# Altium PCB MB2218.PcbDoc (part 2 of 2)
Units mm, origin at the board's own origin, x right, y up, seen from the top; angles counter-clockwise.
Board outline 43 x 47 mm, 4 copper layers (Top Layer, Signal Layer 1, Signal Layer 2, Bottom Layer), stack 1.539 mm thick; 90 components, 71 nets, 361 pads, 605 vias.
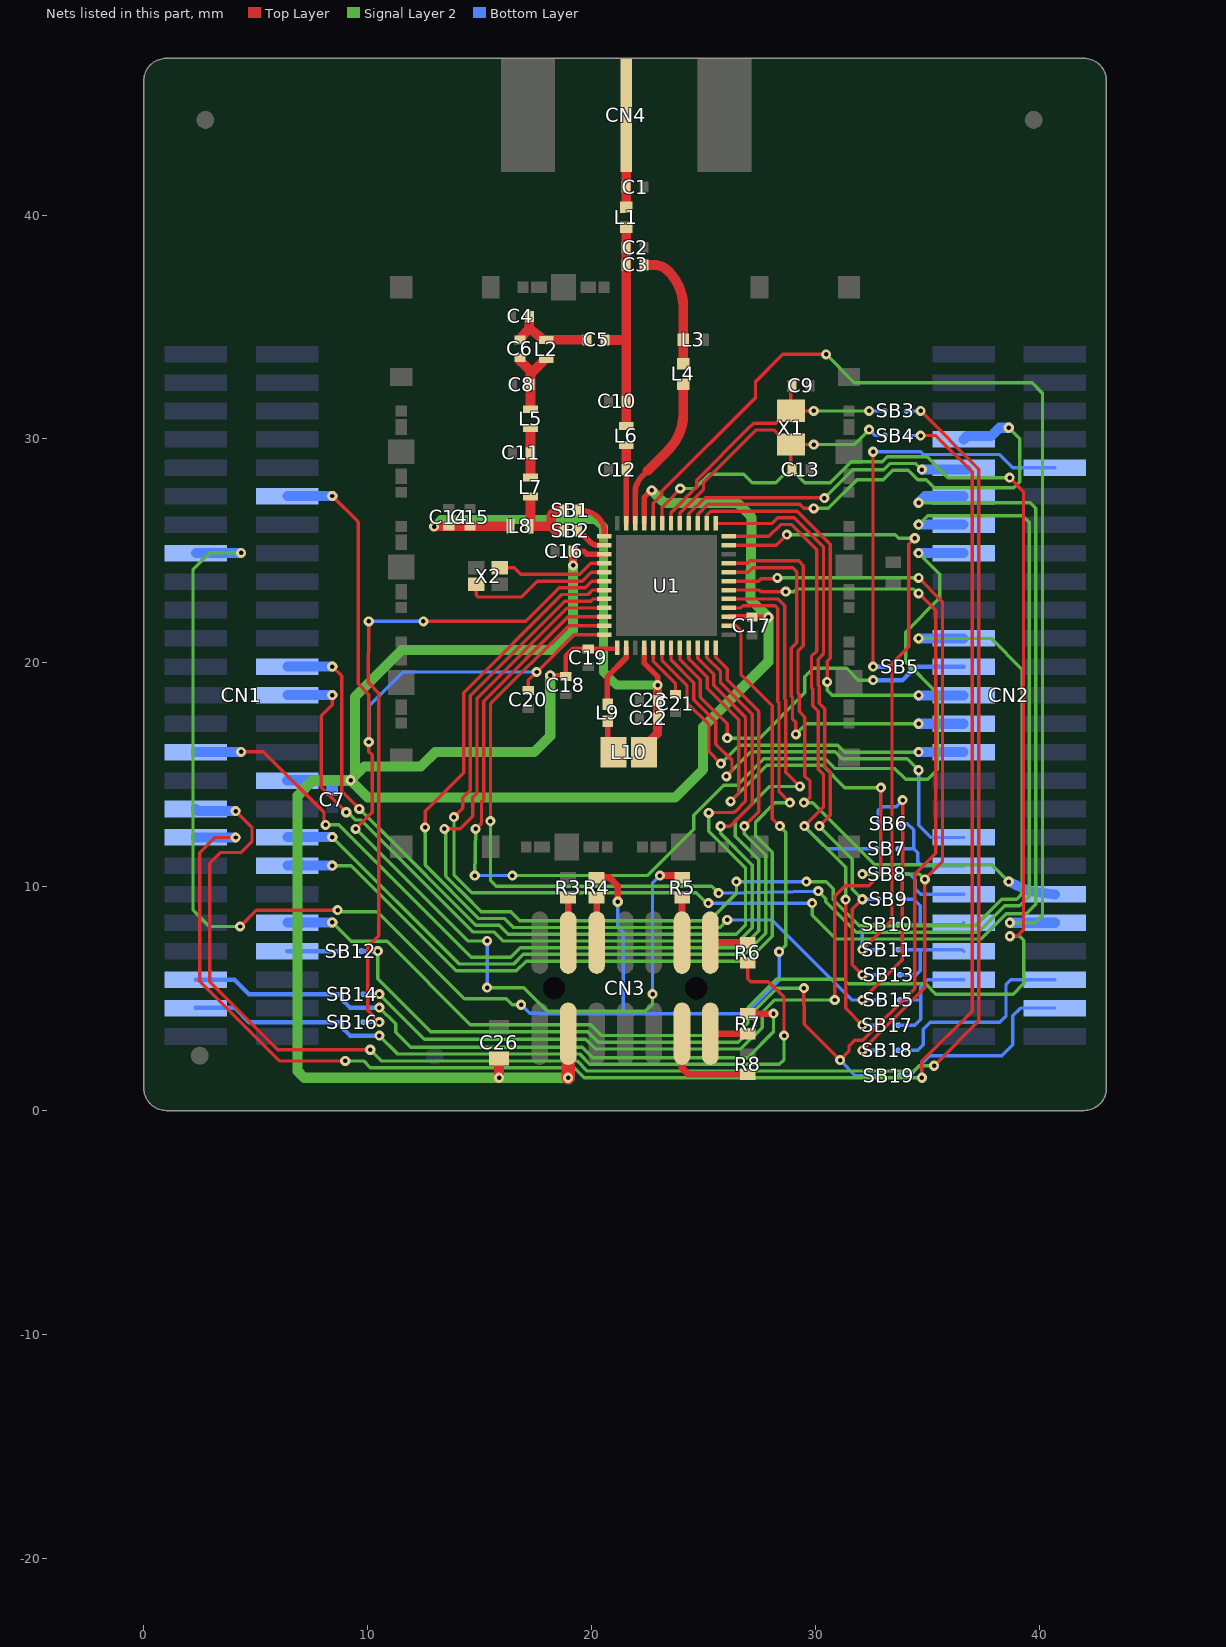
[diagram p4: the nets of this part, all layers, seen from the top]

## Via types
v1: diameter 0.45, hole 0.2, Top Layer to Bottom Layer, tented both sides, 605 vias

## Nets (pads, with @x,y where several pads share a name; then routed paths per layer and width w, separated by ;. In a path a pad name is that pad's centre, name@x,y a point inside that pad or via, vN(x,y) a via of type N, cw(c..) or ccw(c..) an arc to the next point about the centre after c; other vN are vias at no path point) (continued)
GPIO6/SWCLK: CN1.15 R4.2 U1.2 | length 73.1
  Top Layer w0.15: v1(4.301,8.22) 5.033,8.951 v1(8.658,8.951) ; U1.2@26.125,21.65 26.15,21.625 26.493,21.625 26.675,21.443 26.675,19.475 26.779,19.371 28.075,18.075 28.075,13.035 v1(28.41,12.7)
  Top Layer w0.3: R4.2@20.225,10.4 20.231,10.406 20.8,10.406 21.17,10.035 v1(21.17,9.326)
  Signal Layer 2 w0.15: v1(4.301,8.22) 2.931,8.22 2.2,8.951 2.2,24.175 2.935,24.91 v1(4.35,24.91) ; v1(8.658,8.951) 8.739,8.951 8.815,8.875 8.838,8.875 10.367,8.875 cw(c10.367,8.725) 10.473,8.831 10.854,8.45 14.266,5.037 ccw(c14.372,5.144) 14.372,4.994 15.873,5 16.186,5 16.461,4.725 v1(16.855,4.725) ; v1(28.381,7.093) 28.675,7.388 28.675,11.032 28.675,12.435 v1(28.41,12.7)
  Bottom Layer w0.15: v1(16.855,4.725) 17.241,4.339 17.7,4.339 ccw(c17.763,4.475) 17.763,4.325 21.425,4.325 ; v1(21.17,9.326) 21.17,8.212 21.425,7.958 21.425,4.325 ; v1(28.381,7.093) 28.381,5.816 26.889,4.325 21.425,4.325
  Bottom Layer w0.45: CN1.15@2.343,24.91 v1(4.35,24.91)
GPIO11: CN1.24 U1.46 | length 43.9
  Top Layer w0.15: v1(8.42,19.83) 8.838,19.412 8.838,14.265 v1(9.625,13.478) ; U1.46@24.75,20.675 24.75,20.201 25.463,19.489 25.463,18.99 26.875,17.578 26.875,13.811 26.436,13.372 cw(c26.33,13.478) 26.335,13.328 v1(25.236,13.294)
  Signal Layer 2 w0.15: v1(9.625,13.478) 10.434,12.669 10.439,12.669 14.833,8.275 15.873,8.275 16.273,7.875 26.468,7.875 26.875,8.282 26.875,10.838 25.236,12.477 v1(25.236,13.294)
  Bottom Layer w0.45: CN1.24@6.413,19.83 v1(8.42,19.83)
GPIO12: CN1.26 U1.47 | length 43.4
  Top Layer w0.15: v1(8.42,18.56) 8.42,18.124 7.925,17.629 7.925,14.443 v1(9.045,13.323) ; U1.47@25.15,20.675 25.15,20.226 25.763,19.613 25.763,19.114 27.175,17.702 27.175,13.686 26.187,12.699 v1(25.763,12.699)
  Signal Layer 2 w0.15: v1(9.045,13.323) 9.102,13.323 9.445,12.98 9.698,12.98 14.703,7.975 15.635,7.975 16.035,7.575 26.593,7.575 27.175,8.157 27.175,10.963 25.763,12.375 v1(25.763,12.699)
  Bottom Layer w0.45: CN1.26@6.413,18.56 v1(8.42,18.56)
GPIO14: CN1.29 U1.5 | length 49.6
  Top Layer w0.15: v1(4.35,16.02) 5.345,16.02 8.05,13.315 8.05,12.909 8.118,12.841 v1(8.118,12.76) ; U1.5@26.125,22.85 28.323,22.85 28.625,22.548 28.625,18.386 28.675,18.336 28.675,15.11 v1(29.31,14.475)
  Signal Layer 2 w0.15: v1(8.118,12.76) 8.716,12.76 14.631,6.845 16.396,6.845 16.826,7.275 26.717,7.275 27.475,8.033 27.475,11.208 26.425,12.258 26.425,12.936 27.964,14.475 v1(29.31,14.475)
  Bottom Layer w0.45: CN1.29@2.343,16.02 v1(4.35,16.02)
GPIO15/OSC32_IN: CN1.33 SB3.2 | length 77
  Top Layer w0.15: v1(4.101,13.372) 4.818,12.655 4.836,12.655 4.836,12.025 4.336,11.525 3.421,11.525 2.95,11.054 2.95,5.75 5.985,2.715 v1(10.115,2.715) ; v1(34.7,31.25) 37.3,28.65 37.3,4 v1(35.3,2)
  Signal Layer 2 w0.15: v1(10.115,2.715) 10.615,2.215 19.354,2.215 19.804,1.765 34.398,1.765 34.633,2 v1(35.3,2)
  Bottom Layer w0.15: SB3.2@34,31.25 SB3.2@34.075,31.25 v1(34.7,31.25)
  Bottom Layer w0.45: CN1.33@2.331,13.468 2.427,13.372 v1(4.101,13.372)
GPIO16/OSC32_OUT: CN1.35 SB4.2 | length 75.1
  Top Layer w0.15: v1(4.101,12.195) 3.17,12.195 2.5,11.525 2.5,5.776 6.061,2.215 v1(9,2.215) ; v1(34.7,30.15) 35.376,30.15 37,28.526 37,4.437 34.757,2.194 v1(34.757,1.465)
  Signal Layer 2 w0.15: v1(9,2.215) 9.815,2.215 10.115,1.915 19.229,1.915 19.679,1.465 v1(34.757,1.465)
  Bottom Layer w0.15: SB4.2@34,30.15 SB4.2@34.075,30.15 v1(34.7,30.15)
  Bottom Layer w0.45: CN1.35@2.331,12.198 4.098,12.198 v1(4.101,12.195)
GPIO17: CN1.36 U1.48 | length 38.5
  Top Layer w0.15: U1.48@25.55,20.675 25.55,20.25 26.063,19.737 26.063,19.239 27.475,17.826 27.475,13.35 v1(26.825,12.7)
  Signal Layer 2 w0.15: v1(8.42,12.21) 14.085,6.545 16.52,6.545 16.95,6.975 26.841,6.975 27.775,7.909 27.775,11.404 26.825,12.354 v1(26.825,12.7)
  Bottom Layer w0.45: CN1.36@6.413,12.21 v1(8.42,12.21)
GPIO18: CN1.38 U1.4 | length 42.7
  Top Layer w0.15: U1.4@26.125,22.45 26.675,22.45 26.775,22.55 28.199,22.55 28.325,22.424 28.325,18.262 28.375,18.212 28.375,17.869 28.375,17.539 28.375,14.235 v1(28.86,13.75)
  Signal Layer 2 w0.15: v1(8.42,10.94) 9.266,10.94 13.961,6.245 16.644,6.245 17.074,6.675 26.965,6.675 28.075,7.785 28.075,11.528 27.325,12.278 27.325,12.885 28.19,13.75 v1(28.86,13.75)
  Bottom Layer w0.45: CN1.38@6.413,10.94 v1(8.42,10.94)
GPIO21: CN1.42 U1.19 | length 78.9
  Top Layer w0.15: U1.19@23.15,26.225 23.15,26.95 23.552,27.352 ccw(c23.446,27.458) 23.554,27.354 v1(23.964,27.785) ; v1(38.672,28.273) 39.296,27.649 39.296,8.073 39.007,7.784 v1(38.686,7.784)
  Signal Layer 2 w0.15: v1(8.42,8.4) 9.261,7.559 10.866,7.559 14.587,3.838 19.964,3.838 20.451,3.351 26.424,3.351 26.99,3.917 26.99,4.601 28.251,5.862 28.949,5.862 28.953,5.865 31.272,5.865 31.475,5.663 34.92,5.663 35.383,5.2 38.828,5.2 39.312,5.684 39.312,7.598 39.126,7.784 v1(38.686,7.784) ; v1(23.964,27.785) 24.62,27.785 25.23,28.396 cw(c25.313,28.27) 25.313,28.42 26.8,28.42 27.183,28.038 28.228,28.038 28.611,28.42 29.143,28.42 29.526,28.038 30.66,28.038 31.598,28.976 32.981,28.976 33.206,29.2 34.995,29.2 35.923,28.273 v1(38.672,28.273)
  Bottom Layer w0.45: CN1.42@6.413,8.4 v1(8.42,8.4)
GPIO22: CN1.44 SB12.2 | length 2.4
  Bottom Layer w0.2: CN1.44@6.401,7.118 6.408,7.125 SB12.2@8.75,7.125
GPIO23/VCP1_RX: CN1.45 R7.1 SB14.1 | length 30
  Top Layer w0.3: R7.1@26.975,4.325 v1(28.128,4.325)
  Signal Layer 2 w0.15: v1(10.525,4.6) 11.256,3.869 11.256,3.498 11.929,2.825 19.592,2.825 20.052,2.365 26.984,2.365 28.128,3.509 v1(28.128,4.325)
  Bottom Layer w0.2: CN1.45@2.331,5.848 4.052,5.848 4.7,5.2 SB14.1@8.825,5.2 8.835,5.19 8.835,4.974 9.211,4.598 10.523,4.598 v1(10.525,4.6)
GPIO24/VCP1_TX: CN1.47 R6.2 SB16.1 | length 33
  Top Layer w0.15: R6.2@26.975,6.6 26.975,5.882 27.107,5.75 27.899,5.75 28.6,5.049 v1(28.6,3.35)
  Signal Layer 2 w0.15: v1(10.525,3.35) 11.35,2.525 19.468,2.525 19.928,2.065 28.387,2.065 28.6,2.278 v1(28.6,3.35)
  Bottom Layer w0.2: CN1.47@2.331,4.598 4.052,4.598 4.7,3.95 SB16.1@8.825,3.95 8.835,3.94 8.835,3.724 9.211,3.348 10.523,3.348 v1(10.525,3.35)
GPIO28: CN2.7 U1.15 | length 21
  Top Layer w0.15: U1.15@24.75,26.225 24.75,26.624 25.201,27.075 29.31,27.075 29.485,26.9 v1(29.925,26.9)
  Signal Layer 2 w0.15: v1(29.925,26.9) 30.583,26.9 31.858,28.175 33.029,28.175 33.454,28.6 34.148,28.6 34.573,28.175 34.95,28.175 35.302,27.823 38.858,27.823 39.122,28.086 39.122,30.015 v1(38.637,30.5)
  Bottom Layer w0.45: CN2.7@36.621,29.978 36.766,30.123 37.848,30.123 38.225,30.5 v1(38.637,30.5)
GPIO29: CN2.9 U1.16 | length 13.9
  Top Layer w0.15: U1.16@24.35,26.225 24.35,26.649 25.076,27.375 30.378,27.375 v1(30.4,27.353)
  Signal Layer 2 w0.15: v1(30.4,27.353) 31.672,28.625 33.055,28.625 33.33,28.9 34.484,28.9 v1(34.759,28.625)
  Bottom Layer w0.45: v1(34.759,28.625) CN2.9@36.766,28.625
GPIO30: CN2.10 SB5.1 | length 18.7
  Top Layer w0.15: v1(32.575,19.825) v1(32.575,29.426)
  Bottom Layer w0.15: v1(32.575,29.426) 34.708,29.426 34.759,29.375 34.831,29.303 38.229,29.303 38.824,28.708 CN2.10@40.691,28.708
  Bottom Layer w0.2: v1(32.575,19.825) SB5.1@33.3,19.825
GPIO31: CN2.11 U1.32 | length 69.4
  Top Layer w0.15: v1(13.856,13.107) 13.856,13.13 13.879,13.13 14.249,13.5 14.249,13.965 14.585,14.301 14.585,18.535 18.8,22.75 19.967,22.75 20.067,22.85 U1.32@20.575,22.85
  Signal Layer 2 w0.15: v1(13.856,13.107) 13.856,10.525 14.655,9.726 24.684,9.726 25.19,9.22 25.219,9.249 v1(25.219,9.264) ; v1(29.858,9.264) 29.858,8.727 30.924,7.66 37.391,7.66 38.518,8.788 39.413,8.788 39.845,9.22 39.845,26.9 39.595,27.15 v1(34.614,27.15)
  Bottom Layer w0.15: v1(25.219,9.264) v1(29.858,9.264)
  Bottom Layer w0.45: v1(34.614,27.15) 34.902,27.438 CN2.11@36.621,27.438
GPIO33: CN2.13 U1.35 | length 64.1
  Top Layer w0.15: v1(15.485,12.925) 15.485,18.1 cw(c15.635,18.1) 15.529,18.206 18.973,21.65 U1.35@20.575,21.65
  Signal Layer 2 w0.15: v1(15.485,12.925) 15.485,10.291 15.75,10.026 25.361,10.026 v1(25.68,9.708) ; v1(30.127,9.801) 30.467,9.461 30.467,9.318 31.825,7.96 37.266,7.96 38.451,9.145 39.12,9.145 39.545,9.57 39.545,26.273 39.25,26.568 35.014,26.568 34.618,26.172 34.618,26.168 v1(34.614,26.168)
  Bottom Layer w0.15: v1(25.68,9.708) v1(30.127,9.801)
  Bottom Layer w0.45: v1(34.614,26.168) CN2.13@36.621,26.168
GPIO34: CN2.15 U1.34 | length 51.9
  Top Layer w0.15: v1(14.825,12.58) 15.085,12.84 15.085,13.788 15.185,13.888 15.185,18.287 18.949,22.05 U1.34@20.575,22.05
  Signal Layer 2 w0.15: v1(14.784,10.498) v1(14.825,12.58) ; v1(16.461,10.498) 22.489,10.498 24.563,12.571 24.563,13.186 25.902,14.525 26.5,14.525 27.695,15.72 30.443,15.72 30.888,15.275 33.554,15.275 34.029,14.8 35.014,14.8 35.441,15.227 35.441,18.646 34.029,20.058 34.029,21.373 35.562,22.906 35.562,23.95 v1(34.614,24.898)
  Bottom Layer w0.15: v1(14.784,10.498) v1(16.461,10.498)
  Bottom Layer w0.45: v1(34.614,24.898) CN2.15@36.621,24.898
GPIO37: CN2.21 U1.33 | length 62.9
  Top Layer w0.15: v1(13.425,12.58) 14.132,12.58 14.7,13.148 14.7,13.992 14.885,14.177 14.885,18.411 18.924,22.45 U1.33@20.575,22.45
  Signal Layer 2 w0.15: v1(13.425,12.58) 13.483,12.523 13.483,10.474 13.72,10.237 14.284,9.672 15.082,8.875 16.398,8.875 16.798,8.475 25.256,8.475 26.475,9.694 v1(26.475,10.225) ; v1(29.597,10.225) 30.49,10.225 30.8,9.915 30.8,9.409 31.949,8.26 37.142,8.26 38.327,9.445 38.996,9.445 39.245,9.694 39.245,19.696 37.853,21.088 v1(34.614,21.088)
  Bottom Layer w0.15: v1(26.475,10.225) v1(29.597,10.225)
  Bottom Layer w0.45: v1(34.614,21.088) CN2.21@36.621,21.088
GPIO39: CN2.23 SB5.2 U1.44 | length 17.8
  Top Layer w0.15: U1.44@23.95,20.675 23.95,20.15 24.26,19.84 24.263,19.84 24.7,19.403 24.7,19.4 24.863,19.237 24.863,18.471 26.063,17.271 v1(26.063,16.636)
  Signal Layer 2 w0.15: v1(26.063,16.636) 27.508,16.636 29.526,18.654 29.526,19.372 29.906,19.752 31.39,19.752 31.918,19.225 v1(32.575,19.225)
  Bottom Layer w0.2: v1(32.575,19.225) 32.577,19.223 33.889,19.223 34.265,19.599 34.265,19.815 SB5.2@34.275,19.825 ; SB5.2@34.275,19.818 CN2.23@36.621,19.818
GPIO41: CN2.25 U1.14 | length 19.3
  Top Layer w0.15: U1.14@25.15,26.225 25.15,26.599 25.326,26.775 29.186,26.775 30.66,25.301 30.66,20.209 30.525,20.074 v1(30.525,19.151)
  Signal Layer 2 w0.15: v1(30.525,19.151) 30.525,18.776 30.753,18.548 v1(34.614,18.548)
  Bottom Layer w0.45: v1(34.614,18.548) CN2.25@36.621,18.548
GPIO42: CN2.27 U1.8 | length 18.3
  Top Layer w0.15: U1.8@26.125,24.05 26.992,24.05 27.192,24.25 28.987,24.25 29.16,24.077 29.16,20.89 28.925,20.654 28.925,18.51 28.975,18.46 28.975,17.494 29.125,17.344 v1(29.125,16.806)
  Signal Layer 2 w0.15: v1(29.125,16.806) 29.597,17.278 v1(34.614,17.278)
  Bottom Layer w0.45: v1(34.614,17.278) CN2.27@36.621,17.278
GPIO44: CN2.29 U1.42 | length 17.6
  Top Layer w0.15: U1.42@23.15,20.675 23.15,20.101 24.263,18.989 24.263,18.223 25.25,17.236 25.25,16.027 v1(25.777,15.5)
  Signal Layer 2 w0.15: v1(25.777,15.5) 26.597,16.32 31.001,16.32 31.313,16.008 v1(34.614,16.008)
  Bottom Layer w0.45: v1(34.614,16.008) CN2.29@36.621,16.008
GPIO47: CN2.35 U1.43 | length 21.1
  Top Layer w0.15: U1.43@23.55,20.675 23.55,20.126 24.563,19.113 24.563,18.347 25.55,17.36 25.55,16.364 26.275,15.639 26.275,15.174 v1(26.026,14.925)
  Signal Layer 2 w0.15: v1(26.026,14.925) 27.121,16.02 30.876,16.02 31.188,15.708 34.106,15.708 v1(34.614,15.2)
  Bottom Layer w0.15: v1(34.614,15.2) 34.614,12.736 35.152,12.198 CN2.35@36.621,12.198
GPIO49: CN2.37 SB6.2 SB7.1 | length 5
  Bottom Layer w0.15: SB6.2@33.7,12.812 34.114,12.812 34.394,12.532 34.394,11.688 ; SB7.1@33.775,11.688 34.394,11.688 ; CN2.37@36.621,10.928 34.757,10.928 34.569,11.115 34.569,11.512 34.394,11.688
GPIO50: CN2.39 SB8.1 | length 3.5
  Bottom Layer w0.15: SB8.1@33.7,10.563 34.21,10.563 34.275,10.498 34.439,10.334 34.439,9.918 34.699,9.658 CN2.39@36.621,9.658
GPIO51: CN2.40 U1.9 | length 27.3
  Top Layer w0.15: U1.9@26.125,24.45 26.968,24.45 27.068,24.55 29.256,24.55 29.46,24.345 29.46,20.765 29.225,20.53 29.225,18.635 29.275,18.585 29.275,17.826 29.525,17.576 29.525,14.934 29.76,14.699 29.76,13.987 29.523,13.75 v1(29.485,13.75)
  Signal Layer 2 w0.15: v1(29.485,13.75) 29.873,13.75 32.647,10.976 37.886,10.976 v1(38.637,10.225)
  Bottom Layer w0.45: v1(38.637,10.225) 39.521,9.803 CN2.40@40.691,9.658
GPIO52: CN2.41 SB9.2 SB10.1 | length 4.8
  Bottom Layer w0.15: SB10.1@33.7,8.313 34.687,8.313 ; SB9.2@33.775,9.437 34.394,9.437 34.687,9.144 34.687,8.313 ; CN2.41@36.621,8.388 36.546,8.313 34.687,8.313
GPIO53: CN2.42 U1.20 | length 49.2
  Top Layer w0.15: U1.20@22.75,26.225 22.75,27.121 23.142,27.513 23.142,27.663 27.325,31.846 27.325,32.561 28.539,33.775 v1(30.475,33.775)
  Signal Layer 2 w0.15: v1(30.475,33.775) 31.744,32.506 39.688,32.506 40.145,32.049 40.145,8.72 39.813,8.388 v1(38.684,8.388)
  Bottom Layer w0.45: v1(38.684,8.388) CN2.42@40.691,8.388
GPIO54: CN2.43 SB11.1 SB13.2 | length 4.9
  Bottom Layer w0.15: SB11.1@33.7,7.187 34.7,7.187 ; SB13.2@33.775,6.062 34.513,6.062 34.687,6.237 34.687,7.175 34.7,7.187 ; CN2.43@36.621,7.118 36.552,7.187 34.7,7.187
GPIO55: CN2.45 SB15.2 SB17.1 | length 5.5
  Bottom Layer w0.15: SB17.1@33.7,3.812 34.439,3.812 34.7,4.073 34.7,4.95 ; SB15.2@33.775,4.938 34.687,4.938 34.7,4.95 ; CN2.45@36.621,5.848 35.018,5.848 34.7,5.53 34.7,4.95
GPIO56: CN2.46 SB18.1 | length 9.5
  Bottom Layer w0.15: SB18.1@33.7,2.688 34.569,2.688 34.813,2.931 34.813,3.637 35.125,3.95 38.237,3.95 38.517,4.23 38.517,5.642 38.723,5.848 CN2.46@40.691,5.848
GPIO57: CN2.48 SB19.2 | length 8.9
  Bottom Layer w0.15: SB19.2@33.775,1.562 34.218,1.562 35.106,2.45 38.325,2.45 38.817,2.942 38.817,4.233 39.162,4.578 CN2.48@40.691,4.578
NetC1_2: C1.2 CN4.1 L1.2 | length 1.6
  Top Layer w0.44: L1.2@21.55,40.35 C1.2@21.55,41.25 CN4.1@21.55,41.92
NetC2_2: C2.2 C3.2 C5.1 C10.2 L1.1 L6.2 | length 9.7
  Top Layer w0.44: C5.1@20.65,34.425 21.55,34.425 ; L6.2@21.55,30.625 C10.2@21.55,31.675 21.55,34.425 ; 21.55,37.274 21.55,34.425 ; 21.55,37.275 C3.2@21.55,37.775 C2.2@21.55,38.55 L1.1@21.55,39.45
NetC3_1: C3.1 L3.1 L4.2 | length 5.4
  Top Layer w0.44: C3.1@22.45,37.775 22.766,37.775 cw(c22.766,36.836) 23.43,37.5 cw(c21.813,35.883) 24.1,35.883 L3.1@24.1,34.425 L4.2@24.1,33.375
NetC4_2: C4.2 C5.2 C6.2 L2.2 | length 3.2
  Top Layer w0.43: C6.2@16.835,34.488 17.225,34.945 ; C4.2@17.225,35.225 17.225,34.945 ; L2.2@17.8,34.475 17.225,34.945 ; L2.2@17.975,34.425 C5.2@19.6,34.425
NetC6_1: C6.1 C8.2 L2.1 L5.2 | length 3.1
  Top Layer w0.43: C6.1@16.8,33.5 16.825,33.5 16.865,33.46 16.865,33.435 17.275,33.025 17.275,32.425 L5.2@17.275,31.375 ; 17.337,32.963 L2.1@17.85,33.475
NetC9_2: C9.2 SB3.1 U1.18 X1.2 | length 13.4
  Top Layer w0.15: U1.18@23.55,26.225 23.55,26.704 24.7,27.854 24.7,28.161 26.988,30.448 27.239,30.7 28.237,30.7 28.35,30.813 28.35,30.825 28.775,31.25 X1.2@28.9,31.25 ; C9.2@28.9,32.375 X1.2@28.9,31.25 ; v1@30.075,31.25 X1.2@28.9,31.25
  Signal Layer 2 w0.15: v1(29.925,31.25) v1(32.4,31.25)
  Bottom Layer w0.15: v1(32.4,31.25) SB3.1@33.1,31.25
NetC11_2: C11.2 L5.1 L7.2 | length 2.1
  Top Layer w0.43: L7.2@17.275,28.325 17.275,29.375 L5.1@17.275,30.425
NetC12_2: C12.2 L6.1 U1.23 | length 3.3
  Top Layer w0.25: U1.23@21.55,26.225 C12.2@21.55,28.625
  Top Layer w0.44: C12.2@21.55,28.625 21.55,29.55
NetC13_2: C13.2 SB4.1 U1.17 X1.1 | length 13.1
  Top Layer w0.15: U1.17@23.95,26.225 23.95,26.68 25,27.73 25,28.036 27.364,30.4 28.149,30.4 28.35,30.199 28.35,30.175 28.775,29.75 X1.1@28.9,29.75 ; C13.2@28.9,28.625 X1.1@28.9,29.75 ; v1(29.925,29.75) X1.1@28.9,29.75
  Signal Layer 2 w0.15: v1(29.925,29.75) 31.736,29.75 v1(32.4,30.414)
  Bottom Layer w0.15: v1(32.4,30.414) 32.664,30.15 SB4.1@33.1,30.15
NetC21_2: C21.2 U1.41 | length 2.5
  Top Layer w0.15: U1.41@22.75,20.675 22.75,20.077 23.75,19.077 C21.2@23.75,18.625
NetCN3_4: CN3.4 R3.1 | length 2
  Top Layer w0.3: R3.1@18.95,9.5 18.96,9.49 CN3.4@18.96,7.5
NetCN3_6: CN3.6 R4.1 | length 2
  Top Layer w0.3: R4.1@20.225,9.5 20.23,9.495 CN3.6@20.23,7.5
NetCN3_11: CN3.11 R8.2 | length 4.6
  Top Layer w0.3: CN3.11@24.04,3.43 24.04,1.897 24.312,1.625 R8.2@26.975,1.625
NetCN3_12: CN3.12 R5.1 | length 2
  Top Layer w0.3: CN3.12@24.04,7.5 24.04,9.49 R5.1@24.05,9.5
NetCN3_13: CN3.13 R7.2 | length 1.7
  Top Layer w0.3: CN3.13@25.31,3.43 25.315,3.425 R7.2@26.975,3.425
NetCN3_14: CN3.14 R6.1 | length 1.7
  Top Layer w0.3: CN3.14@25.31,7.5 R6.1@26.975,7.5
NetL4_1: L4.1 U1.22 | length 6.9
  Top Layer w0.25: U1.22@21.95,26.225 21.95,27.601 cw(c22.974,27.601) 22.25,28.325 22.5,28.575
  Top Layer w0.44: 22.5,28.575 23.43,29.505 ccw(c21.813,31.122) 24.1,31.122 L4.1@24.1,32.425
NetL7_1: L7.1 L8.2 SB1.2 SB2.2 | length 3.6
  Top Layer w0.43: L7.1@17.275,27.375 17.275,26.1 18.193,26.1 ; SB2.2@18.575,25.9 18.393,25.9 18.193,26.1 ; SB1.2@18.575,26.8 18.401,26.8 18.193,26.592 18.193,26.1
NetL9_1: L9.1 U1.38 | length 2.9
  Top Layer w0.25: L9.1@20.725,18.152 20.707,18.17 20.707,19.382 21.55,20.225 U1.38@21.55,20.675
NetL9_2: L9.2 L10.2 | length 1.5
  Top Layer w0.25: L9.2@20.725,17.394 20.725,16.27 L10.2@20.987,16.008
NetSB1_1: SB1.1 U1.25 | length 1.8
  Top Layer w0.25: SB1.1@19.375,26.8 19.528,26.8 cw(c19.528,25.69) 20.312,26.475 cw(c19.679,25.841) 20.575,25.841 20.575,25.75
NetSB2_1: SB2.1 U1.26 | length 1.4
  Top Layer w0.25: SB2.1@19.375,25.9 cw(c19.375,25.746) 19.484,25.855 19.945,25.394 ccw(c20.292,25.74) 20.292,25.25 U1.26@20.575,25.25
NetSB6_1: SB6.1 SB15.1 U1.31 | length 51.1
  Top Layer w0.15: v1(12.565,12.65) 12.565,13.363 14.285,15.083 14.285,18.659 18.676,23.05 19.843,23.05 20.043,23.25 U1.31@20.575,23.25 ; v1(32.1,4.938) 33.844,6.681 ccw(c33.738,6.787) 33.888,6.787 v1(33.9,13.862)
  Signal Layer 2 w0.15: v1(12.565,12.65) 12.565,10.968 14.957,8.575 16.12,8.575 16.52,8.175 25.726,8.175 v1(26.062,8.511)
  Bottom Layer w0.15: v1(26.062,8.511) 28.051,8.511 31.625,4.938 v1(32.1,4.938) SB15.1@32.8,4.938 ; SB6.1@32.8,12.812 32.8,13.405 32.97,13.575 33.613,13.575 33.886,13.849 cw(c33.992,13.743) 33.889,13.851 v1(33.9,13.862)
NetSB7_2: SB7.2 SB17.2 U1.12 | length 31.9
  Top Layer w0.15: U1.12@26.125,25.65 27.924,25.65 28.449,26.175 28.938,26.175 29.875,25.238 30.06,25.052 30.06,20.517 29.825,20.282 29.825,18.883 29.875,18.833 29.875,18.075 30.125,17.825 30.125,15.25 30.36,15.014 30.36,13.549 v1(29.511,12.7) ; v1(31.35,9.425) 31.35,4.562 v1(32.1,3.812)
  Signal Layer 2 w0.15: v1(29.511,12.7) 31.35,10.861 v1(31.35,9.425)
  Bottom Layer w0.15: v1(29.511,12.7) 30.524,11.688 SB7.2@32.725,11.688 ; v1(32.1,3.812) SB17.2@32.725,3.812
NetSB8_2: SB8.2 SB18.2 U1.7 | length 35.7
  Top Layer w0.15: U1.7@26.125,23.65 27.461,23.65 27.561,23.75 28.261,23.75 v1(28.3,23.789) ; v1(32.1,2.688) 34.889,5.477 v1(34.889,10.325) 35.676,11.112 35.676,22.731 v1(34.614,23.793)
  Signal Layer 2 w0.15: v1(28.3,23.789) 28.304,23.793 v1(34.614,23.793) ; v1(32.1,10.563) 34.652,10.563 v1(34.889,10.325)
  Bottom Layer w0.15: v1(32.1,2.688) SB18.2@32.725,2.688 ; v1(32.1,10.563) SB8.2@32.725,10.563
NetSB9_1: SB9.1 SB13.1 U1.13 | length 27.7
  Top Layer w0.15: U1.13@25.55,26.225 28.075,26.225 28.325,26.475 29.062,26.475 30.175,25.362 30.36,25.177 30.36,20.393 30.125,20.157 30.125,19.007 30.175,18.958 30.175,18.199 30.425,17.949 30.425,15.374 30.66,15.139 30.66,13.185 v1(30.175,12.7) ; v1(32.1,6.062) 31.65,6.512 31.65,8.988 v1(32.1,9.437)
  Signal Layer 2 w0.15: v1(30.175,12.7) 31.65,11.225 31.65,9.887 v1(32.1,9.437)
  Bottom Layer w0.15: v1(32.1,6.062) SB13.1@32.8,6.062 ; v1(32.1,9.437) SB9.1@32.8,9.437
NetSB10_2: SB10.2 SB11.2 U1.11 | length 30.2
  Top Layer w0.15: U1.11@26.125,25.25 28.25,25.25 v1(28.725,25.725) ; v1(32.1,7.187) 33.425,8.513 33.425,19.976 34.164,20.715 34.164,25.289 v1(34.439,25.564)
  Signal Layer 2 w0.15: v1(28.725,25.725) 33.561,25.725 33.723,25.564 v1(34.439,25.564)
  Bottom Layer w0.15: SB11.2@32.725,7.187 v1(32.1,7.187) 32.1,8.137 32.275,8.313 SB10.2@32.725,8.313
NetSB12_1: SB12.1 SB19.1 U1.6 | length 61.2
  Top Layer w0.15: U1.6@26.125,23.25 27.491,23.25 27.523,23.219 ; 27.523,23.218 ccw(c27.628,23.325) 27.629,23.175 v1(28.674,23.178) ; v1(29.485,5.465) 29.5,3.911 ccw(c29.65,3.912) 29.543,3.807 v1(31.1,2.25) 31.5,2.65 31.5,2.875 31.763,3.137 32.126,3.137 34.438,5.449 34.438,5.813 34.439,5.813 34.439,10.551 35.376,11.487 35.376,22.338 v1(34.614,23.1)
  Signal Layer 2 w0.15: v1(10.45,7.125) 10.45,5.888 12.825,3.512 19.839,3.512 20.301,3.051 26.548,3.051 27.29,3.792 27.29,4.477 28.278,5.465 v1(29.485,5.465) ; v1(28.674,23.178) 29.034,23.178 29.151,23.295 34.385,23.295 34.58,23.1 v1(34.614,23.1)
  Bottom Layer w0.15: v1(31.1,2.25) 31.788,1.562 SB19.1@32.8,1.562
  Bottom Layer w0.2: SB12.1@9.725,7.125 v1(10.45,7.125)
NetSB14_2: SB14.2 U1.45 | length 50.1
  Top Layer w0.15: U1.45@24.35,20.675 24.35,20.177 25.163,19.364 25.163,18.866 26.575,17.454 26.575,14.173 v1(26.213,13.811) ; v1(30.863,4.938) 30.863,9.574 31.324,10.035 32.385,10.035 32.925,10.575 v1(32.925,14.425)
  Signal Layer 2 w0.15: v1(10.525,5.2) 12.538,3.187 19.74,3.187 20.176,2.751 26.672,2.751 27.629,3.707 27.629,4.391 28.175,4.938 v1(30.863,4.938) ; v1(26.213,13.811) 26.213,13.814 27.819,15.42 30.319,15.42 31.314,14.425 v1(32.925,14.425)
  Bottom Layer w0.2: SB14.2@9.8,5.2 v1(10.525,5.2)
NetSB16_2: SB16.2 U1.30 | length 30.4
  Top Layer w0.15: v1@10.05,21.775 10.026,19.182 ccw(c10.176,19.181) 10.07,19.076 10.5,18.646 10.5,7.811 10,7.311 10,4.475 v1(10.525,3.95) ; v1(12.49,21.85) 17.051,21.85 18.552,23.35 19.718,23.35 20.018,23.65 U1.30@20.575,23.65
  Bottom Layer w0.15: SB16.2@9.8,3.95 v1(10.525,3.95) ; v1(10.05,21.85) v1(12.49,21.85)
NetU1_28: U1.28 X2.3 | length 5.1
  Top Layer w0.15: X2.3@16.005,24.15 X2.3@15.905,24.25 16.543,24.25 16.843,23.95 19.47,23.95 19.97,24.45 U1.28@20.575,24.45
NetU1_29: U1.29 X2.1 | length 6.7
  Top Layer w0.15: X2.1@14.855,23.5 14.855,23.025 14.943,22.938 16.866,22.938 17.579,23.65 19.594,23.65 19.994,24.05 U1.29@20.575,24.05
NRST: C20.2 CN1.12 R5.2 U1.36 | length 57.2
  Top Layer w0.15: v1(8.42,27.45) 9.534,26.336 ; v1(9.462,12.58) 10.2,13.318 10.2,15.883 10.05,16.033 v1(10.05,16.462) 10.05,18.58 9.575,19.055 9.575,23.034 ; 9.535,26.335 cw(c9.427,26.231) 9.577,26.231 9.576,23.035 ; C20.2@17.172,18.802 17.172,19.213 v1(17.547,19.588) 19.209,21.25 U1.36@20.575,21.25
  Top Layer w0.3: v1(23.055,10.498) 23.952,10.498 R5.2@24.05,10.4
  Signal Layer 2 w0.15: v1(9.462,12.58) 14.467,7.575 v1(15.338,7.575) ; v1(15.338,5.494) 15.344,5.488 16.979,5.488 18.029,4.437 22.404,4.437 22.725,4.758 v1(22.725,5.199)
  Bottom Layer w0.15: v1(10.05,16.462) 10.05,18.063 11.575,19.588 v1(17.547,19.588) ; v1(15.338,5.494) v1(15.338,7.575) ; v1(22.725,5.199) 22.725,10.167 v1(23.055,10.498)
  Bottom Layer w0.45: CN1.12@6.413,27.45 v1(8.42,27.45)
VDD: C7.2 C16.2 C17.2 C18.2 C19.2 C26.2 CN1.32 CN3.3 U1.3 U1.21 U1.27 U1.37 | length 108.2
  Top Layer w0.2: v1@18.159,19.438 18.163,19.441 C18.2@18.852,19.441 ; C18.2@18.852,19.39 C18.2@18.852,19.441 ; C18.2@18.878,19.444 18.875,19.441 C18.2@18.852,19.441 ; U1.37@21.15,20.675 21.15,20.625 C19.2@19.857,20.625 19.853,20.629 19.161,20.629 18.852,20.32 C18.2@18.852,19.441
  Top Layer w0.25: C16.2@19.175,24.985 19.655,24.985 19.79,24.85 U1.27@20.575,24.85 ; U1.21@22.35,26.225 22.35,27.38 22.669,27.699 v1(22.692,27.699) ; U1.3@26.125,22.05 C17.2@27.163,22.05 27.171,22.042 27.892,22.042 v1(27.899,22.035) ; C17.2@27.119,22.025 C17.2@27.163,21.981
  Top Layer w0.35: v1(19.175,24.35) C16.2@19.175,24.985
  Top Layer w0.45: v1(15.875,1.465) C26.2@15.875,2.325
  Top Layer w0.6: v1(18.958,1.465) 18.96,1.468 CN3.3@18.96,3.43
  Signal Layer 2 w0.45: v1@9.238,14.75 7.563,14.75 6.875,14.062 6.875,1.75 7.16,1.465 v1(15.875,1.465) v1(18.958,1.465) ; v1(18.156,19.434) 18.156,16.73 17.434,16.008 13.014,16.008 12.381,15.375 9.858,15.375 9.427,14.943 ; 19.088,21.33 18.325,20.567 11.522,20.567 9.427,18.472 9.427,14.943 ; 19.088,21.33 ccw(c18.875,21.541) 19.175,21.541 v1(19.175,24.35) ; v1(22.692,27.699) 23.162,27.228 ; 23.163,27.228 ccw(c23.375,27.441) 23.375,27.141 26.409,27.141 cw(c26.409,26.841) 26.621,27.053 27.06,26.614 ; 23.824,14.074 23.737,13.987 10.005,13.987 v1(9.238,14.754) 9.427,14.943 ; 23.825,14.075 24.985,15.235 24.985,17.128 27.899,20.042 v1(27.899,22.035) 27.104,22.83 27.104,23.45 27.147,26.398 ccw(c26.847,26.403) 27.116,26.535 27.115,26.537 ccw(c26.847,26.403) 27.061,26.613
  Bottom Layer w0.45: CN1.32@6.401,14.738 6.417,14.754 8.363,14.754 ; CN1.32@6.425,14.762 7.571,14.759 CN1.32@7.583,14.759 ; 8.42,14.697 8.363,14.754 ; v1(9.238,14.754) 8.363,14.754
  Bottom Layer w0.5: C7.2@8.42,14.407 8.42,14.697
VFBSD: C14.1 C15.2 C22.2 C23.1 L8.1 L10.1 U1.40 | length 25.4
  Top Layer w0.25: U1.40@22.35,20.675 22.35,19.982 22.951,19.381 v1(22.951,19)
  Top Layer w0.4: L10.1@22.356,15.571 L10.1@22.356,15.672 ; L10.1@22.376,16.275 22.95,16.85 C23.1@22.95,18.321 22.95,18.571 v1(22.951,19) v1@22.951,19.049
  Top Layer w0.43: v1(12.964,26.084) 12.969,26.084 12.985,26.1 L8.1@16.325,26.1
  Signal Layer 2 w0.4: v1(12.964,26.084) 13.28,26.4 20.198,26.4 20.539,26.059 20.539,19.588 21.127,19 v1(22.951,19)
pads on no net: CART-1.1 CN1.2 CN1.3 CN1.4 CN1.5 CN1.8 CN1.10 CN1.11 CN1.16 CN1.18 CN1.19 CN1.20 CN1.21 CN1.23 CN1.27 CN1.30 CN1.39 CN1.41 CN1.43 CN1.48 CN1.50 CN2.1 CN2.3 CN2.4 CN2.5 CN2.6 CN2.12 CN2.16 CN2.17 CN2.18 CN2.19 CN2.22 CN2.24 CN2.28 CN2.30 CN2.31 CN2.33 CN2.34 CN2.36 CN2.47 CN2.49 CN3.1 CN3.2 CN3.8 CN3.9 CN3.10 CN3.NPTH1 CN3.NPTH2 MIRE-1.1 MIRE-2.1 MIRE-3.1 MIRE-4.1 MIRE-5.1 MIRE-6.1

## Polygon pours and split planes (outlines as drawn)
GND on Top Layer "GND_L01_P001" (solid, remove dead copper, pour order 1): 0,47 43,47 43,0 0,0
GND on Top Layer "GND_L01_P004" (solid, remove dead copper, pour order 4): 14.496,29.375 14.5,29.371 14.5,27.35 14.787,27.063 16.625,27.063 16.625,29.375
GND on Signal Layer 1 "GND_L02_P000" (solid, remove dead copper, pour order 0): 0,47 43,47 43,0 0,0
GND on Signal Layer 2 "GND_L03_P002" (solid, remove dead copper, pour order 2): 0,47 43,47 43,0 0,0
GND on Bottom Layer "GND_L04_P003" (solid, remove dead copper, pour order 3): 0,47 43,47 43,0 0,0

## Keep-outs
Top Layer:
  region: 17.275,31.891 15.284,31.891 cw(c15.284,32.425) 14.75,32.425 cw(c15.275,32.425) 15.275,32.95 17.275,32.95
  region: 14.155,23.87 14.08,23.87 cw(c14.08,24.25) 13.7,24.25 cw(c14.075,24.25) 14.075,24.625 15.225,24.625 15.225,23.875
  region: 24.75,34.959 26.091,34.959 cw(c26.091,34.425) 26.625,34.425 cw(c26.1,34.425) 26.1,33.9 24.75,33.9 24.75,34.05
  region: 21.5,31.141 19.559,31.141 cw(c19.559,31.675) 19.025,31.675 cw(c19.55,31.675) 19.55,32.2 21.5,32.2
  region: 14.041,26.75 14.041,28.091 cw(c14.575,28.091) 14.575,28.625 cw(c14.575,28.1) 15.1,28.1 15.1,26.75 14.95,26.75
  region: 17.275,28.841 15.284,28.841 cw(c15.284,29.375) 14.75,29.375 cw(c15.275,29.375) 15.275,29.9 17.275,29.9
  region: 16.625,34.941 15.284,34.941 cw(c15.284,35.475) 14.75,35.475 cw(c15.275,35.475) 15.275,36 16.625,36 16.625,35.85
  region: 21.55,28.091 19.559,28.091 cw(c19.559,28.625) 19.025,28.625 cw(c19.55,28.625) 19.55,29.15 21.55,29.15
  region: 13.091,26.75 13.091,28.091 cw(c13.625,28.091) 13.625,28.625 cw(c13.625,28.1) 14.15,28.1 14.15,26.75 14,26.75
Keep-Out Layer:
  region: 15.861,25.525 cw(c15.861,24.599) 16.78,24.719 ccw(c17.456,24.886) 16.958,24.4 ccw(c17.418,26.736) 17.728,24.375 17.97,24.375 cw(c17.864,24.041) 18.214,24.037 18.188,22.05 14.149,22.05 14.149,22.25 17.625,22.25 ccw(c17.625,22.5) 17.875,22.5 17.875,23.817 17.728,23.964 17.257,23.964 cw(c17.257,24.846) 16.384,24.719 ccw(c15.854,24.72) 15.854,25.25 14.149,25.25 14.149,25.525
  region: 4.5,45 4.5,43.5 9.75,43.5 9.75,45

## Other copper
Top Layer:
  pour cut-out: 19.423,17.403 19.423,15.072 24.25,15.072 24.25,17.369
  region net GND: 16.183,26.75 16.615,26.75 16.615,26.915
  pour cut-out: 16.615,26.568 16.615,26.75 13.903,26.75 13.903,26.568
  pour cut-out: 17.822,27.433 17.822,27.093 19.86,27.093 19.86,27.433
  pour cut-out: 18.139,18.802 19.419,18.802 19.419,16.22 18.139,16.22
  pour cut-out: 18.14,18.401 16,18.402 16,19.411 18.156,19.434
  pour cut-out: 24.25,17.369 25.029,17.369 25.029,17.141 24.25,17.141
  pour cut-out: 13.865,24.825 13.617,24.577 13.617,23.738 14.647,22.708 15.261,22.708 15.261,24.823
  region net GND: 22.351,18.663 21.207,18.663 21.207,17.063 22.35,17.063
  region net GND: 21.425,18.602 21.798,18.602 21.798,18.311 21.798,17.253 21.798,17.244 21.425,17.244
  pour cut-out: 28.5,32.938 28.588,33.025 30.193,33.025 30.309,32.909 30.309,28.089 30.313,28.085 30.29,28.062 28.128,28.062 27.924,28.266 27.924,32.362
  text "1" at 4.959,43.768 h1.5
Signal Layer 1:
  text "2" at 6.181,43.768 h1.5
Signal Layer 2:
  text "3" at 8.065,43.776 h1.5
Bottom Layer:
  text "4" at 9.333,43.77 h1.5

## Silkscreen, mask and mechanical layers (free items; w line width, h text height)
Top Overlay:
  lines w0.12: 19.75,25.975 20,26.225 20,26.546 20.354,26.9 22.527,26.9 ; 22.05,47 22.825,47
  text "J" at 31.675,41.686 h10
  text "MB2218A" at 30.963,39.013 h2.3
  text "H" at 7.912,38.4 h10
  text "K" at 2.052,38.289 h8
  text "RX_WAKEUP" at 23.552,37.718 h1.3
  text "C" at 1.36,6.215 h8
  text "E" at 8.115,6.008 h9
  text "I" at 36.886,3.613 h10
Top Solder:
  rectangle: 4.5,43.5 9.75,45
Bottom Solder:
  rectangle: 4.5,43.5 9.75,45
M1-Board Shape:
  the board outline again, w0.1
Drill Drawing:
  drawing of 186 lines, arcs and shapes, not listed
  text "PCB SPECIFICATIONS :" at -22.541,97.137 h3
  text "A.   MATERIAL :" at -22.541,93.137 h3
  text "FR-4" at 15.959,93.137 h3
  text "TG-170" at 32.459,93.137 h3
  text "X  TG-150" at 50.709,93.137 h3
  text "TG-140" at 66.709,93.137 h3
  text "B.   MATERIAL FAMILY :" at -22.541,90.137 h3
  text "Ventec VT/47" at 15.959,90.137 h3
  text "C.   SOLDERMASK COLOR :" at -22.541,87.137 h3
  text "GREEN" at 15.959,87.137 h3
  text "X  BLUE" at 32.459,87.137 h3
  text "RED" at 50.709,87.137 h3
  text "BLACK" at 66.709,87.137 h3
  text "D.   SILKSCREEN COLOR :" at -22.541,84.137 h3
  text "X  WHITE" at 15.959,84.137 h3
  text "YELLOW" at 32.459,84.137 h3
  text "BLACK" at 50.709,84.137 h3
  text "E.   SURFACE FINISH :" at -22.541,81.137 h3
  text "X  ENIG" at 15.959,81.137 h3
  text "IMMERSION SILVER" at 32.459,81.137 h3
  text "IMMERSION TIN" at 66.709,81.137 h3
  text "HASL" at 15.959,78.137 h3
  text "HASL (PB-FREE)" at 32.459,78.137 h3
  text "GOLDEN FINGER" at 66.709,78.137 h3
  text "F.   IMPEDANCE CONTROL :" at -22.541,75.137 h3
  text "NO" at 15.959,75.137 h3
  text "X  YES" at 32.459,75.137 h3
  text "G.   THROUGH VIA :" at -22.541,72.137 h3
  text "PLUG THE VIAS WHICH ARE COVERED WITH SOLDERMASK ONE OR TWO SIDE." at 15.959,72.137 h3
  text "PLUG MATERIAL :" at 15.959,69.137 h3
  text "X  SOLDERMASK" at 41.459,69.137 h3
  text "NON-CONDUCTIVE EPOXY." at 66.709,69.137 h3
  text "H.   STACK-UP :" at -22.541,66.137 h3
  text "SEE LAYER STACK-UP SEQUENCE FOR OVERALL THICKNESS." at 15.959,66.137 h3
  text "Layer" at 50.841,59.1 h1.8
  text "Name" at 58.372,59.1 h1.8
  text "Material" at 72.928,59.1 h1.8
  text "Thickness" at 86.013,59.1 h1.8
  text "Constant" at 96.758,59.1 h1.8
  text "PCB : TYPE 3" at 110.088,57.996 h3
  text "Top Overlay" at 58.372,55.5 h1.8
  text "ASPECT-RATIO, AXE Z :" at 110.088,52.496 h3
  text "Top Solder" at 58.372,51.9 h1.8
  text "Solder Resist" at 72.928,51.9 h1.8
  text "0.010mm" at 86.013,51.9 h1.8
  text "3.5" at 96.758,51.9 h1.8
  text "1" at 50.841,48.3 h1.8
  text "Top Layer" at 58.372,48.3 h1.8
  text "Copper" at 72.928,48.3 h1.8
  text "0.041mm" at 86.013,48.3 h1.8
  text "6 :1 à 8 :1 / LEVEL \"B\"" at 110.107,45.749 h3
  text "Dielectric 1" at 58.372,44.7 h1.8
  text "FR4 VT-47" at 72.928,44.7 h1.8
  text "0.254mm" at 86.013,44.7 h1.8
  text "4" at 96.758,44.7 h1.8
  text "2" at 50.84,41.1 h1.8
  text "Signal Layer 1" at 58.372,41.1 h1.8
  text "Copper" at 72.928,41.1 h1.8
  text "0.018mm" at 86.013,41.1 h1.8
  text "Dielectric 2" at 58.372,37.5 h1.8
  text "FR4 VT-47" at 72.928,37.5 h1.8
  text "0.914mm" at 86.013,37.5 h1.8
  text "4.3" at 96.758,37.5 h1.8
  text "3" at 50.841,33.9 h1.8
  text "Signal Layer 2" at 58.372,33.9 h1.8
  text "Copper" at 72.928,33.9 h1.8
  text "0.018mm" at 86.013,33.9 h1.8
  text "MINIMUN PARAMETERS" at 109.5,32.02 h3
  text "Dielectric 3" at 58.372,30.3 h1.8
  text "FR4 VT-47" at 72.928,30.3 h1.8
  text "0.254mm" at 86.013,30.3 h1.8
  text "4" at 96.758,30.3 h1.8
  text "4" at 50.841,26.7 h1.8
  text "Bottom Layer" at 58.372,26.7 h1.8
  text "Copper" at 72.928,26.7 h1.8
  text "0.041mm" at 86.013,26.7 h1.8
  text "DEFAULT" at 109.5,26.52 h3
  text "Bottom Solder" at 58.372,23.1 h1.8
  text "Solder Resist" at 72.928,23.1 h1.8
  text "0.010mm" at 86.013,23.1 h1.8
  text "3.5" at 96.758,23.1 h1.8
  text "TRACKS : 0.150mm           / GAPS : 0.150mm" at 109.5,20.77 h3
  text "Bottom Overlay" at 58.372,19.5 h1.8
  text "Symbol" at 51.124,12.705 h2.16
  text "Count" at 59.578,12.705 h2.16
  text "Hole Size" at 68.353,12.705 h2.16
  text "Plated" at 83.773,12.705 h2.16
  text "Hole Type" at 91.198,12.705 h2.16
  text "Drill Layer Pair" at 102.002,12.705 h2.16
  text "Via/Pad" at 122.471,12.705 h2.16
  text "Hole Length" at 131.326,12.705 h2.16
  text "605" at 59.578,8.977 h1.8
  text "0.20mm (7.87mil)" at 68.353,8.977 h1.8
  text "PTH" at 83.773,8.977 h1.8
  text "Round" at 91.198,8.977 h1.8
  text "Top Layer - Bottom Layer" at 102.002,8.977 h1.8
  text "Via" at 122.471,8.977 h1.8
  text "-" at 131.326,8.977 h1.8
  text "2" at 59.578,5.249 h1.8
  text "1.00mm (39.37mil)" at 68.353,5.249 h1.8
  text "NPTH" at 83.773,5.249 h1.8
  text "Round" at 91.198,5.249 h1.8
  text "Top Layer - Bottom Layer" at 102.002,5.249 h1.8
  text "Pad" at 122.471,5.249 h1.8
  text "-" at 131.326,5.249 h1.8
  text "607 Total" at 59.578,1.522 h1.8

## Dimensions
1,0 to 1,47 on M2-Board Dimensions
0,1 to 43,1 on M2-Board Dimensions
